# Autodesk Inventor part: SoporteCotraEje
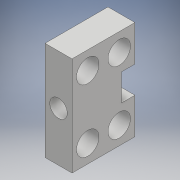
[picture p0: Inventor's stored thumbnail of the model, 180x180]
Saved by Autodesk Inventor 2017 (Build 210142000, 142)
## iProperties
Part Number: SoporteCotraEje
Material: Genérico
Document SubType Name: Modeling
Designer: Diego
Density: 1 g/cm^3
Appearance: Valor por defecto
Author: Diego
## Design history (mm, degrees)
derived "Lubina.ipt"
feature "Sólido17::Lubina.ipt" dims "d0" = 10
tag "OperaciónIdentificador1"
node "Sólido1"
